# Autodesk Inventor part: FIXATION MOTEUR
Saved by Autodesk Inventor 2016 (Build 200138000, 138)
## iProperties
Created: 2013-10
Part Number: FIXATION MOTEUR
Material: Générique
Document SubType Name: Modeling
Designer: Bruno
Density: 1 g/cm^3
Appearance: Par défaut
Author: Bruno
Sending System: SolidWorks 2013
Last Author: christophe
Last Saved: 2014-02-15
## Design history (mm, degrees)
feature "Enlèv. mat.-Extru.1"
node "Solide1"
